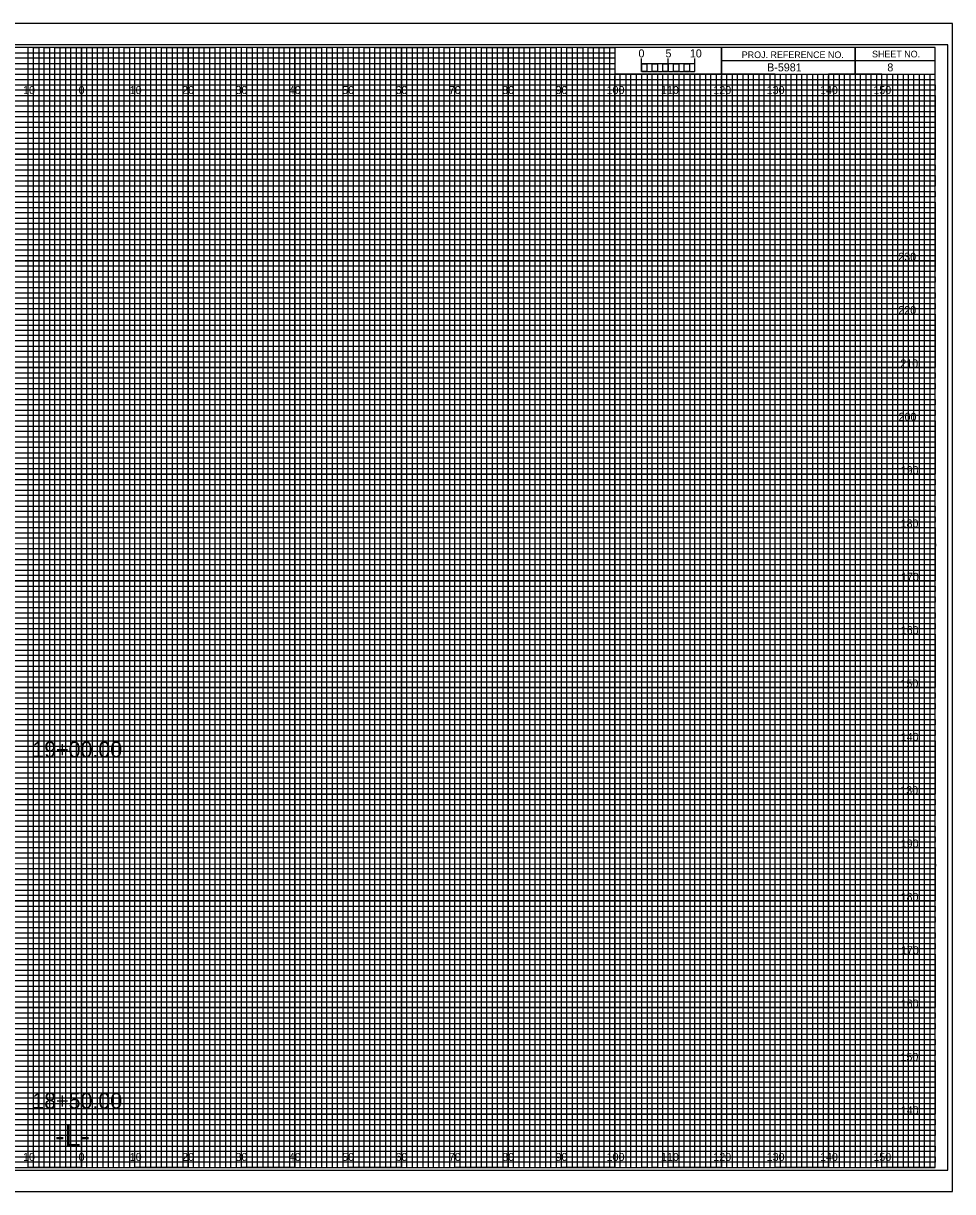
# Model space of a CAD drawing. Extents: x -13 to 323, y -5 to 1754.
# Drawn here: x 149.1 to 323.3, y 875.5 to 1094.5 of the extents above; entities that cross this region are included whole.
import ezdxf

# ---------------------------------------------------------------- set-up
doc = ezdxf.new("R2010")
doc.units = 0
for name, color, linetype in [('Exist Cross Section Cell', 7, 'Continuous'), ('Exist XS Center Line Elevation Label', 7, 'Continuous'), ('Exist XS Ground Line', 7, 'Continuous'), ('Prop CMT Concrete Structures', 7, 'Continuous'), ('Prop CMT Guardrail Graphics', 7, 'Continuous'), ('Prop CMT Pvmt Course 1', 7, 'Continuous'), ('Prop CMT Pvmt Course 2', 7, 'Continuous'), ('Prop CMT Pvmt Course 3', 7, 'Continuous'), ('Prop CMT Pvmt Surface', 7, 'Continuous'), ('Prop CMT Shld Paved Course 1', 7, 'Continuous'), ('Prop CMT Shld Paved Course 2', 7, 'Continuous'), ('Prop CMT Shld Paved Course 3', 7, 'Continuous'), ('Prop CMT Subgrade Earthwork', 7, 'Continuous'), ('Prop XS Ditch Standard Text', 7, 'Continuous'), ('Prop XS SE Text', 7, 'Continuous'), ('Prop XS Side Slope Text', 7, 'Continuous'), ('Scratch_Level_0', 7, 'Continuous')]:
    doc.layers.add(name, color=color, linetype=linetype)

msp = doc.modelspace()

# ---------------------------------------------------------------- linework, layer by layer
at = {"layer": 'Exist XS Center Line Elevation Label'}
for points in [[(145, 880), (155, 880), (155, 1090), (165, 1090), (165, 880), (175, 880), (175, 1090), (185, 1090), (185, 880), (195, 880), (195, 1090), (205, 1090), (205, 880), (215, 880), (215, 1090), (225, 1090), (225, 880), (235, 880), (235, 1090), (245, 1090), (245, 880), (255, 880), (255, 1090), (259.93, 1090), (260, 1090), (260, 1085), (264.99, 1085), (264.99, 880), (275, 880), (275, 1085), (285, 1085), (285, 880), (295, 880), (295, 1085), (305, 1085), (305, 880), (315, 880), (315, 1085)], [(0, 1085), (275, 1085)], [(0, 1065), (320, 1065), (320, 1075), (0, 1075)], [(0, 1045), (320, 1045), (320, 1055), (0, 1055)], [(0, 1025), (320, 1025), (320, 1035), (0, 1035)], [(0, 1005), (320, 1005), (320, 1015), (0, 1015)], [(0, 985), (320, 985), (320, 995), (0, 995)], [(0, 965), (320, 965), (320, 975), (0, 975)], [(0, 945), (320, 945), (320, 955), (0, 955)], [(0, 925), (320, 925), (320, 935), (0, 935)], [(0, 905), (320, 905), (320, 915), (0, 915)], [(0, 885), (320, 885), (320, 895), (0, 895)]]:
    msp.add_lwpolyline(points, dxfattribs=at)
at = {"layer": 'Exist XS Ground Line'}
for p, q in [((150, 1090), (140, 1090)), ((150, 880), (150, 1090)), ((170, 1090), (160, 1090)), ((160, 1090), (160, 880)), ((170, 880), (170, 1090)), ((190, 1090), (180, 1090)), ((180, 1090), (180, 880)), ((190, 880), (190, 1090)), ((210, 1090), (200, 1090)), ((200, 1090), (200, 880)), ((210, 880), (210, 1090)), ((230, 1090), (220, 1090)), ((220, 1090), (220, 880)), ((230, 880), (230, 1090)), ((250, 1090), (240, 1090)), ((240, 1090), (240, 880)), ((250, 880), (250, 1090)), ((260, 1090), (260, 880)), ((270, 880), (270, 1085)), ((290, 1085), (280, 1085)), ((280, 1085), (280, 880)), ((290, 880), (290, 1085)), ((310, 1085), (300, 1085)), ((300, 1085), (300, 880)), ((310, 880), (310, 1085)), ((160, 880), (150, 880)), ((180, 880), (170, 880)), ((200, 880), (190, 880)), ((220, 880), (210, 880)), ((240, 880), (230, 880)), ((260, 880), (250, 880)), ((280, 880), (270, 880)), ((300, 880), (290, 880)), ((320, 880), (310, 880)), ((320, 880), (320, 880))]:
    msp.add_line(p, q, dxfattribs=at)
for points in [[(0, 1080), (320, 1080), (320, 1070), (0, 1070)], [(0, 1060), (320, 1060), (320, 1050), (0, 1050)], [(0, 1040), (320, 1040), (320, 1030), (0, 1030)], [(0, 1020), (320, 1020), (320, 1010), (0, 1010)], [(0, 1000), (320, 1000), (320, 990), (0, 990)], [(0, 980), (320, 980), (320, 970), (0, 970)], [(0, 960), (320, 960), (320, 950), (0, 950)], [(0, 940), (320, 940), (320, 930), (0, 930)], [(0, 920), (320, 920), (320, 910), (0, 910)], [(0, 900), (320, 900), (320, 890), (0, 890)]]:
    msp.add_lwpolyline(points, dxfattribs=at)
at = {"layer": 'Prop CMT Pvmt Course 1'}
for p, q in [((323.3, 1094.5), (-13.4, 1094.5)), ((-13.4, 875.5), (323.3, 875.5))]:
    msp.add_line(p, q, dxfattribs=at)
at = {"layer": 'Prop CMT Pvmt Course 2'}
msp.add_lwpolyline([(-13.4, 875.5), (323.3, 875.5), (323.3, 1094.5), (-13.4, 1094.5)], close=True, dxfattribs=at)
at = {"layer": 'Prop CMT Pvmt Course 3'}
msp.add_lwpolyline([(-10.8, 879.5), (322.4, 879.5), (322.4, 1090.5), (-10.8, 1090.5)], close=True, dxfattribs=at)
at = {"layer": 'Prop CMT Shld Paved Course 1'}
for p, q in [((305, 1090), (305, 1085)), ((305, 1085), (305, 1090)), ((280, 1087.5), (280, 1085)), ((320, 1087.49), (280, 1087.49)), ((280, 1085), (320, 1085))]:
    msp.add_line(p, q, dxfattribs=at)
for points in [[(320, 1090), (0, 1090), (0, 880), (320, 880)], [(280, 1090), (260, 1090), (260, 1085.03), (280, 1085.03)], [(320, 1090), (280, 1090), (280, 1085), (320, 1085)]]:
    msp.add_lwpolyline(points, close=True, dxfattribs=at)
at = {"layer": 'Prop CMT Shld Paved Course 2'}
for p, q in [((267, 1085), (266.01, 1085)), ((266.01, 1085), (266.01, 880)), ((267, 880), (267, 1085)), ((269, 1085), (268, 1085)), ((268, 1085), (268, 880)), ((269, 880), (269, 1085)), ((266.01, 880), (265, 880)), ((268, 880), (267, 880))]:
    msp.add_line(p, q, dxfattribs=at)
for points in [[(150, 880), (151, 880), (151, 1090), (152, 1090), (152, 880)], [(152, 880), (153, 880), (153, 1090), (154, 1090), (154, 880)], [(155, 880), (156, 880), (156, 1090), (157, 1090), (157, 880)], [(157, 880), (158, 880), (158, 1090), (159, 1090), (159, 880)], [(160, 880), (161, 880), (161, 1090), (162, 1090), (162, 880)], [(162, 880), (163, 880), (163, 1090), (164, 1090), (164, 880)], [(165, 880), (166, 880), (166, 1090), (167, 1090), (167, 880)], [(167, 880), (168, 880), (168, 1090), (169, 1090), (169, 880)], [(170, 880), (171, 880), (171, 1090), (172, 1090), (172, 880)], [(172, 880), (173, 880), (173, 1090), (174, 1090), (174, 880)], [(175, 880), (176, 880), (176, 1090), (177, 1090), (177, 880)], [(177, 880), (178, 880), (178, 1090), (179, 1090), (179, 880)], [(180, 880), (181, 880), (181, 1090), (182, 1090), (182, 880)], [(182, 880), (183, 880), (183, 1090), (184, 1090), (184, 880)], [(185, 880), (186, 880), (186, 1090), (187, 1090), (187, 880)], [(187, 880), (188, 880), (188, 1090), (189, 1090), (189, 880)], [(190, 880), (191, 880), (191, 1090), (192, 1090), (192, 880)], [(192, 880), (193, 880), (193, 1090), (194, 1090), (194, 880)], [(195, 880), (196, 880), (196, 1090), (197, 1090), (197, 880)], [(197, 880), (198, 880), (198, 1090), (199, 1090), (199, 880)], [(200, 880), (201, 880), (201, 1090), (202, 1090), (202, 880)], [(202, 880), (203, 880), (203, 1090), (204, 1090), (204, 880)], [(205, 880), (206, 880), (206, 1090), (207, 1090), (207, 880)], [(207, 880), (208, 880), (208, 1090), (209, 1090), (209, 880)], [(210, 880), (211, 880), (211, 1090), (212, 1090), (212, 880)], [(212, 880), (213, 880), (213, 1090), (214, 1090), (214, 880)], [(215, 880), (216, 880), (216, 1090), (217, 1090), (217, 880)], [(217, 880), (218, 880), (218, 1090), (219, 1090), (219, 880)], [(220, 880), (221, 880), (221, 1090), (222, 1090), (222, 880)], [(222, 880), (223, 880), (223, 1090), (224, 1090), (224, 880)], [(225, 880), (226, 880), (226, 1090), (227, 1090), (227, 880)], [(227, 880), (228, 880), (228, 1090), (229, 1090), (229, 880)], [(230, 880), (231, 880), (231, 1090), (232, 1090), (232, 880)], [(232, 880), (233, 880), (233, 1090), (234, 1090), (234, 880)], [(235, 880), (236, 880), (236, 1090), (237, 1090), (237, 880)], [(237, 880), (238, 880), (238, 1090), (239, 1090), (239, 880)], [(240, 880), (241, 880), (241, 1090), (242, 1090), (242, 880)], [(242, 880), (243, 880), (243, 1090), (244, 1090), (244, 880)], [(245, 880), (246, 880), (246, 1090), (247, 1090), (247, 880)], [(247, 880), (248, 880), (248, 1090), (249, 1090), (249, 880)], [(250, 880), (251, 880), (251, 1090), (252, 1090), (252, 880)], [(252, 880), (253, 880), (253, 1090), (254, 1090), (254, 880)], [(255, 880), (256, 880), (256, 1090), (257, 1090), (257, 880)], [(257, 880), (258, 880), (258, 1090), (259, 1090), (259, 880)], [(260, 880), (261, 880), (261, 1085), (262.02, 1085), (262.02, 880)], [(262, 880), (263, 880), (263, 1085), (263.99, 1085), (263.99, 880)], [(270, 880), (270.98, 880), (270.98, 1085), (272, 1085), (272, 880)], [(272, 880), (273, 880), (273, 1085), (274.05, 1085), (274.05, 880)], [(275, 880), (276, 880), (276, 1085), (277, 1085), (277, 880)], [(277, 880), (278, 880), (278, 1085), (279, 1085), (279, 880)], [(280, 880), (281, 880), (281, 1085), (282, 1085), (282, 880)], [(282, 880), (283, 880), (283, 1085), (284, 1085), (284, 880)], [(285, 880), (286, 880), (286, 1085), (287, 1085), (287, 880)], [(287, 880), (288, 880), (288, 1085), (289, 1085), (289, 880)], [(290, 880), (291, 880), (291, 1085), (292, 1085), (292, 880)], [(292, 880), (293, 880), (293, 1085), (294, 1085), (294, 880)], [(295, 880), (296, 880), (296, 1085), (297, 1085), (297, 880)], [(297, 880), (298, 880), (298, 1085), (299, 1085), (299, 880)], [(300, 880), (301, 880), (301, 1085), (302, 1085), (302, 880)], [(302, 880), (303, 880), (303, 1085), (304, 1085), (304, 880)], [(305, 880), (306, 880), (306, 1085), (307, 1085), (307, 880)], [(307, 880), (308, 880), (308, 1085), (309, 1085), (309, 880)], [(310, 880), (311, 880), (311, 1085), (312, 1085), (312, 880)], [(312, 880), (313, 880), (313, 1085), (314, 1085), (314, 880)], [(315, 880), (316, 880), (316, 1085), (317, 1085), (317, 880)], [(317, 880), (318, 880), (318, 1085), (319, 1085), (319, 880)]]:
    msp.add_lwpolyline(points, dxfattribs=at)
at = {"layer": 'Prop CMT Shld Paved Course 3'}
for p, q in [((265, 1085.49), (265, 1087.9)), ((265, 1086.9), (265, 1087.9)), ((270, 1085.49), (270, 1087.9)), ((275, 1085.49), (275, 1087.9)), ((275, 1086.9), (275, 1087.9))]:
    msp.add_line(p, q, dxfattribs=at)
for points in [[(275, 1086.9), (265, 1086.9), (265, 1085.49), (275, 1085.49)], [(265, 1086.9), (266, 1086.9), (266, 1085.49), (265, 1085.49)], [(267, 1086.9), (268, 1086.9), (268, 1085.49), (267, 1085.49)], [(269, 1086.9), (270, 1086.9), (270, 1085.49), (269, 1085.49)], [(271, 1086.9), (272, 1086.9), (272, 1085.49), (271, 1085.49)], [(273, 1086.9), (274, 1086.9), (274, 1085.49), (273, 1085.49)]]:
    msp.add_lwpolyline(points, close=True, dxfattribs=at)
at = {"layer": 'Prop CMT Subgrade Earthwork'}
for p, q in [((150, 880), (150, 1090)), ((160, 880), (160, 1090)), ((170, 880), (170, 1090)), ((180, 880), (180, 1090)), ((190, 880), (190, 1090)), ((200, 880), (200, 1090)), ((210, 880), (210, 1090)), ((220, 880), (220, 1090)), ((230, 880), (230, 1090)), ((240, 880), (240, 1090)), ((250, 880), (250, 1090)), ((260, 880), (260, 1084.69)), ((270, 880), (270, 1084.69)), ((280, 880), (280, 1084.69)), ((290, 880), (290, 1084.69)), ((300, 880), (300, 1084.69)), ((310, 880), (310, 1084.69)), ((0, 1080), (320, 1080)), ((0, 1070), (320, 1070)), ((0, 1060), (320, 1060)), ((0, 1050), (320, 1050)), ((0, 1040), (320, 1040)), ((0, 1030), (320, 1030)), ((0, 1020), (320, 1020)), ((0, 1010), (320, 1010)), ((0, 1000), (320, 1000)), ((0, 990), (320, 990)), ((0, 980), (320, 980)), ((0, 970), (320, 970)), ((0, 960), (320, 960)), ((0, 950), (320, 950)), ((0, 940), (320, 940)), ((0, 930), (320, 930)), ((0, 920), (320, 920)), ((0, 910), (320, 910)), ((0, 900), (320, 900)), ((0, 890), (320, 890))]:
    msp.add_line(p, q, dxfattribs=at)
at = {"layer": 'Scratch_Level_0'}
for p, q in [((0, 1089), (260, 1089)), ((260, 1089), (260, 1087.98)), ((260, 1087.98), (0, 1087.98)), ((0, 1087), (260, 1087)), ((260, 1087), (260, 1085.89)), ((260, 1085.89), (0, 1085.89)), ((0, 1084), (320, 1084))]:
    msp.add_line(p, q, dxfattribs=at)
for points in [[(0, 1083), (270, 1083), (320, 1083), (320, 1082), (0, 1082)], [(0, 1081), (320, 1081), (320, 1079), (0, 1079)], [(0, 1078), (320, 1078), (320, 1077), (0, 1076.98)], [(0, 1076), (320, 1076), (320, 1074), (0, 1074)], [(0, 1073), (320, 1073), (320, 1072), (0, 1072)], [(0, 1071), (320, 1071), (320, 1069), (0, 1069)], [(0, 1068), (320, 1068), (320, 1067), (0, 1067)], [(0, 1066), (320, 1066), (320, 1064), (0, 1064)], [(0, 1063), (320, 1063), (320, 1062), (0, 1062)], [(0, 1061), (320, 1061), (320, 1059), (0, 1059)], [(0, 1058), (320, 1058), (320, 1057), (0, 1057)], [(0, 1056), (320, 1056), (320, 1053.95), (320, 1053), (320, 1052), (0, 1052)], [(0, 1054), (320, 1054), (320, 1053), (0, 1053)], [(0, 1051), (320, 1051), (320, 1049), (0, 1049.03)], [(0, 1049.03), (320, 1049), (320, 1048), (0, 1048)], [(0, 1047), (320, 1047), (320, 1046), (0, 1046)], [(0, 1044), (320, 1044), (320, 1043), (0, 1043)], [(0, 1042), (320, 1042), (320, 1041), (0, 1041)], [(-0.07, 1038.89), (320, 1038.89), (320, 1037.88), (-0.07, 1037.88)], [(0, 1037), (320, 1037), (320, 1036), (0, 1036)], [(0, 1034), (320, 1034), (320, 1033), (0, 1033)], [(0, 1032), (320, 1032), (320, 1031), (0, 1031)], [(0, 1029), (320, 1029), (320, 1028), (0, 1028)], [(0, 1027), (320, 1027), (320, 1026), (0, 1026)], [(0, 1024), (320, 1024), (320, 1023), (0, 1023)], [(0, 1022), (320, 1022), (320, 1021), (0, 1021)], [(0, 1019), (320, 1019), (319.99, 1017.98), (0, 1018)], [(0, 1017), (320, 1017), (320, 1016), (0, 1016)], [(0, 1014), (320, 1014), (320, 1013), (0, 1013)], [(0, 1012), (320, 1012), (320, 1011), (0, 1011)], [(0, 1009), (320, 1009), (320, 1008), (0, 1008)], [(0, 1007), (320, 1007), (320, 1006), (0, 1006)], [(0, 1004), (320, 1004), (320, 1003), (0, 1003)], [(0, 1002), (320, 1002), (320, 1001), (0, 1001)], [(0, 999), (320, 999), (320, 998), (0, 998)], [(0, 996.99), (320.07, 996.91), (320, 996), (0, 996)], [(0, 994), (320, 994), (320, 993), (0, 993)], [(0, 992), (320, 992), (320, 991), (0, 991)], [(0, 989), (320, 989), (320, 988), (0, 988)], [(0, 987), (320, 987), (320, 986), (0, 986)], [(0, 984), (320, 984), (320, 983), (0, 983)], [(0, 982), (320, 982), (320, 981), (0, 981)], [(0, 979), (320, 979), (320, 978), (0, 978)], [(0, 977), (320, 977), (320, 976), (0, 976)], [(0, 974), (320, 974), (320, 973), (0, 973)], [(0, 972), (320, 972), (320, 971), (0, 971)], [(0, 969), (320, 969), (320, 968), (0, 968)], [(0, 967), (320, 967), (320, 966), (0, 966)], [(0, 964), (320, 964), (320, 963), (0, 963)], [(0, 962), (320, 962), (320, 961), (0, 961)], [(0, 959), (320, 959), (319.99, 957.98), (0, 958)], [(0, 957), (320, 957), (320, 956), (0, 956)], [(0, 954), (320, 954), (320, 953), (0, 953)], [(0, 952), (320, 952), (320, 951), (0, 951)], [(0, 949), (320, 949), (320, 948), (0, 948)], [(0, 947), (320, 947), (320, 946), (0, 946)], [(0, 944), (320, 944), (320, 943), (0, 943)], [(0, 942), (320, 942), (320, 941), (0, 941)], [(0, 939), (320, 939), (320, 938), (0, 938)], [(0, 936.99), (320.07, 936.91), (320, 936), (0, 936)], [(0, 934), (320, 934), (320, 933), (0, 933)], [(0, 932), (320, 932), (320, 931), (0, 931)], [(0, 929), (320, 929), (320, 928), (0, 928)], [(0, 927), (320, 927), (320, 926), (0, 926)], [(0, 924), (320, 924), (320, 923), (0, 923)], [(0, 922), (320, 922), (320, 921), (0, 921)], [(0, 919), (320, 919), (320, 918), (0, 918)], [(0, 917), (320, 917), (320, 916), (0, 916)], [(0, 914), (320, 914), (320, 913), (0, 913)], [(0, 912), (320, 912), (320, 911), (0, 911)], [(0, 909), (320, 909), (320, 908), (0, 908)], [(0, 907), (320, 907), (320, 906), (0, 906)], [(0, 904), (320, 904), (320, 903), (0, 903)], [(0, 902), (320, 902), (320, 901), (0, 901)], [(0, 899), (320, 899), (320, 898), (0, 898)], [(0, 897), (320, 897), (320, 896), (0, 896)], [(0, 894), (320, 894), (320, 893), (0, 893)], [(0, 892), (320, 892), (320, 891), (0, 891)], [(0, 889), (320, 889), (320, 888), (0, 888)], [(0, 887), (320, 887), (320, 886), (0, 886)], [(0, 884), (320, 884), (320, 883), (0, 883)], [(0, 882), (320, 882), (320, 881), (0, 881)]]:
    msp.add_lwpolyline(points, dxfattribs=at)

# ---------------------------------------------------------------- texts
at = {"layer": 'Exist Cross Section Cell'}
for s, p in [('230', (313.11, 1050)), ('220', (313.12, 1040)), ('210', (313.5, 1030)), ('200', (313.17, 1020)), ('190', (313.57, 1010)), ('180', (313.55, 1000)), ('170', (313.61, 990)), ('160', (313.57, 980)), ('150', (313.52, 970)), ('140', (313.57, 960)), ('130', (313.49, 950)), ('190', (313.57, 940)), ('180', (313.55, 930)), ('170', (313.61, 920)), ('160', (313.57, 910)), ('150', (313.52, 900)), ('140', (313.57, 890))]:
    msp.add_text(s, height=1.5, dxfattribs=at).set_placement(p)
at = {"layer": 'Prop CMT Concrete Structures'}
msp.add_text('8', height=1.5, dxfattribs=at).set_placement((311.06, 1085.5))
at = {"layer": 'Prop CMT Guardrail Graphics'}
for s, p in [('5', (269.47, 1088.12)), ('10', (274.04, 1088.12))]:
    msp.add_text(s, height=1.5, dxfattribs=at).set_placement(p)
at = {"layer": 'Prop CMT Pvmt Surface'}
for s, p in [('19+00.00', (150.77, 956.89)), ('18+50.00', (150.77, 891.04))]:
    msp.add_text(s, height=3, dxfattribs=at).set_placement(p)
at = {"layer": 'Prop CMT Shld Paved Course 1'}
for s, p in [('PROJ. REFERENCE NO.', (283.77, 1087.99)), ('SHEET NO.', (308.19, 1088.12))]:
    msp.add_text(s, height=1.25, dxfattribs=at).set_placement(p)
at = {"layer": 'Prop CMT Shld Paved Course 3'}
msp.add_text('0', height=1.5, dxfattribs=at).set_placement((264.41, 1088.12))
at = {"layer": 'Prop XS Ditch Standard Text'}
for s, p in [('10', (149.04, 1081.25)), ('0', (159.45, 1081.25)), ('0', (159.45, 1081.25)), ('10', (169.04, 1081.25)), ('20', (178.86, 1081.25)), ('30', (188.86, 1081.25)), ('40', (198.86, 1081.25)), ('50', (208.86, 1081.25)), ('60', (218.86, 1081.25)), ('70', (228.86, 1081.25)), ('80', (238.86, 1081.25)), ('90', (248.86, 1081.25)), ('100', (258.44, 1081.25)), ('110', (268.62, 1081.25)), ('120', (278.44, 1081.25)), ('130', (288.44, 1081.25)), ('140', (298.44, 1081.25)), ('150', (308.44, 1081.25)), ('10', (149.04, 881.25)), ('0', (159.45, 881.25)), ('0', (159.45, 881.25)), ('10', (169.04, 881.25)), ('20', (178.86, 881.25)), ('30', (188.86, 881.25)), ('40', (198.86, 881.25)), ('50', (208.86, 881.25)), ('60', (218.86, 881.25)), ('70', (228.86, 881.25)), ('80', (238.86, 881.25)), ('90', (248.86, 881.25)), ('100', (258.44, 881.25)), ('110', (268.62, 881.25)), ('120', (278.44, 881.25)), ('130', (288.44, 881.25)), ('140', (298.44, 881.25)), ('150', (308.44, 881.25))]:
    msp.add_text(s, height=1.5, dxfattribs=at).set_placement(p)
at = {"layer": 'Prop XS SE Text'}
msp.add_text('-L-', height=4, dxfattribs=at).set_placement((155.06, 884))
at = {"layer": 'Prop XS Side Slope Text'}
msp.add_text('B-5981', height=1.5, dxfattribs=at).set_placement((288.53, 1085.5))

doc.saveas('drawing.dxf')
